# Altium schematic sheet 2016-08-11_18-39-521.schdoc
size 304 x 134 mm; SheetNumber: 1; SheetTotal: 1
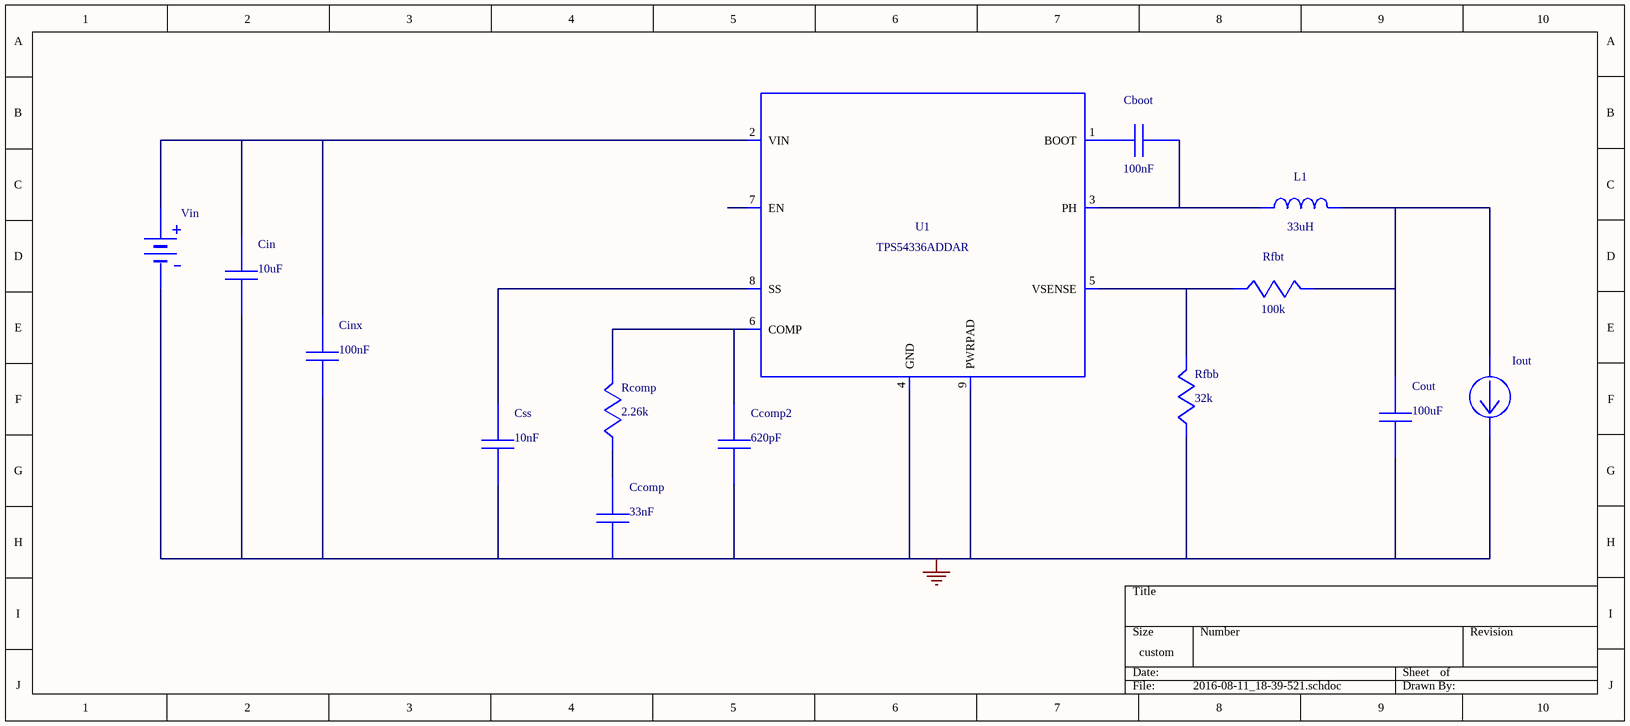
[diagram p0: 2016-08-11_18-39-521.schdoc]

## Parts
Cboot  value 100nF  (hidden comment: C0805C104K5RACTU)
Ccomp  value 33nF  (hidden comment: GRM033R60J333KE01D)
Ccomp2  value 620pF  (hidden comment: CL21C621JBCNNNC)
Cin  value 10uF  (hidden comment: GRM32ER7YA106KA12L)
Cinx  value 100nF  (hidden comment: C0805C104K5RACTU)
Cout  value 100uF  (hidden comment: GRM31CR60J107ME39L)
Css  value 10nF  (hidden comment: GRM033R61A103KA01D)
Iout  WB_CURRENT_LOAD  (value not drawn)
L1  value 33uH  (hidden comment: SRN8040-330M)
Rcomp  value 2.26k  (hidden comment: CRCW04022K26FKED)
Rfbb  value 32k  (hidden comment: RT0805BRD0732KL)
Rfbt  value 100k  (hidden comment: CRCW0402100KFKED)
U1  TPS54336DDAR  (value not drawn)
Vin  WB_BATTERY  (value not drawn)

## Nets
0: Ccomp.2 Ccomp2.2 Cin.2 Cinx.2 Cout.2 Css.2 Iout.2(-) Rfbb.2 U1.4(GND) U1.9(PWRPAD) Vin.2(-)
NetCboot_1: Cboot.1 U1.1(BOOT)
NetCboot_2: Cboot.2 L1.1 U1.3(PH)
NetCcomp2_1: Ccomp2.1 Rcomp.1 U1.6(COMP)
NetCcomp_1: Ccomp.1 Rcomp.2
NetCin_1: Cin.1 Cinx.1 U1.2(VIN) Vin.1(+)
NetCout_1: Cout.1 Iout.1(+) L1.2 Rfbt.1
NetCss_1: Css.1 U1.8(SS)
NetRfbb_1: Rfbb.1 Rfbt.2 U1.5(VSENSE)

Not connected (* = marked no-connect by the designer): U1 7(EN)

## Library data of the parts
Cboot Cinx = C0805C104K5RACTU: Manufacturer Name: Kemet
Ccomp = GRM033R60J333KE01D: GRM033R60J333KE0; Manufacturer Name: MuRata
Ccomp2 = CL21C621JBCNNNC: Manufacturer Name: Samsung Electro-Mechanics
Cin = GRM32ER7YA106KA12L: GRM32ER7YA106KA1; Manufacturer Name: MuRata
Cout = GRM31CR60J107ME39L: GRM31CR60J107ME3; Manufacturer Name: MuRata
Css = GRM033R61A103KA01D: GRM033R61A103KA0; Manufacturer Name: MuRata
L1 = SRN8040-330M: Manufacturer Name: Bourns
Rcomp = CRCW04022K26FKED: Manufacturer Name: Vishay-Dale
Rfbb = RT0805BRD0732KL: Manufacturer Name: Yageo America
Rfbt = CRCW0402100KFKED: Manufacturer Name: Vishay-Dale
U1 = TPS54336DDAR: TPS54336ADDAR; Manufacturer Name: Texas Instruments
